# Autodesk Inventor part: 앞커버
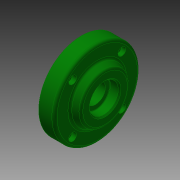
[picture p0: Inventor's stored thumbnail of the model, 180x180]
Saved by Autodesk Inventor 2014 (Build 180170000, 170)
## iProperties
Company: 한국ATC센터
Created: 2015-12
Part Number: 앞커버
Document SubType Name: Modeling
Designer: 앞커버
Density: 2.71 g/cm^3
Mass: 114.339 g
Surface Area: 117.889 cm^2
Volume: 42.1916 cm^3
Material: 알루미늄 6061
Appearance: 진녹색
Author: mdu
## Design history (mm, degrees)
sketch "스케치1"
  geometry: L1 (-11.5, 0)-(11.5, 0); L2 (11.5, 0)-(11.5, 22.5); L3 (11.5, 22.5)-(6.5, 22.5); L4 (6.5, 22.5)-(6.5, 32.5); L5 (6.5, 32.5)-(-5.5, 32.5); L6 (-5.5, 32.5)-(-5.5, 21); L7 (-5.5, 21)-(-11.5, 18.202); L8 (-11.5, 18.202)-(-11.5, 0); 2 further points
  constraints: 16 end point, 3 parallel, 3 perpendicular, 1 coincident, 1 horizontal, 1 midpoint
  dimensions: "d0" = 23 distance of L1.start L1.end; "d1" = 65 diameter of L5 L1; "d2" = 45 diameter of L3 L1; "d3" = 42 diameter of L6.end L1; "d4" = 115 deg angle of L7 L6; "d5" = 12 distance of L4.end L5.end; "d6" = 5 distance of L2.end L3.end
revolve "회전1" sketch "스케치1" stored, may be unused: angle "d7" = 90 deg
sketch "스케치2"
  geometry: L1 (0, 0)-(32.5, 0); L2 (0, 0)-(18.738, 18.738); 1 further point
  constraints: 4 end point, 1 horizontal, 1 horizontal alignment, 1 other
  dimensions: "d8" = 45 deg angle of L1 L2; "d9" = 26.5 distance of L1.start L2.end
hole "구멍1" sketch "스케치2" at (18.738, 18.738) diameter "d10" = 3.4; stored, may be unused: countersink angle "d14" = 90 deg, drill point angle "d16" = 118 deg; dims "d11" = 6, "d12" = 6, "d13" = 3.3, "d15" = 8
fillet "모깎기1" dims "d20" = 2
hole "구멍2" diameter "d23" = 15; stored, may be unused: countersink angle "d27" = 90 deg, drill point angle "d29" = 118 deg; dims "d21" = 10, "d22" = 10, "d24" = 6, "d25" = 32, "d26" = 10, "d28" = 8
hole "구멍3" diameter "d32" = 22; stored, may be unused: countersink angle "d36" = 90 deg, drill point angle "d38" = 0 deg; dims "d30" = 10, "d31" = 10, "d33" = 6, "d34" = 32, "d35" = 10, "d37" = 7.3
chamfer "모따기1" distance "d39" = 1; stored, may be unused: second distance "d40" = 2, angle "d41" = 45 deg
fillet "모깎기2" dims "d42" = 0.3
node "솔리드1"
pattern_circular "원형 패턴1" dims angle "d18" = 360 deg
